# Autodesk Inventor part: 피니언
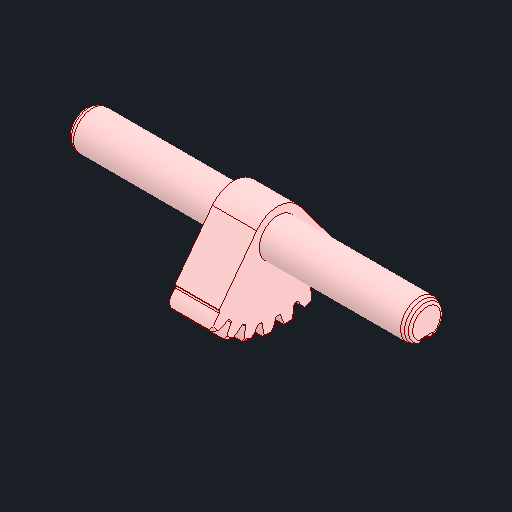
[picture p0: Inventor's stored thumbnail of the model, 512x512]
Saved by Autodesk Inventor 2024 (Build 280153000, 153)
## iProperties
Created: 2024-05
Part Number: 피니언
Material: 강철, 탄소
Document SubType Name: Modeling
Designer: kh_501
Density: 7.85 g/cm^3
Appearance: 기본값
Sending System: Autodesk Inventor 2025
Preprocessor: ST-DEVELOPER v20
Author: jhkim
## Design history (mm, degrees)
node "피니언1"
node "솔리드2"
node "솔리드1"
